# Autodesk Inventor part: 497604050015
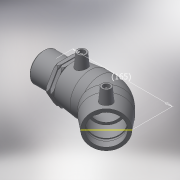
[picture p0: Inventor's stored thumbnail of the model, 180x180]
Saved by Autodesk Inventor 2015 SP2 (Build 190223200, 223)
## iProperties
Created: 2017-06
Part Number: 497604050015
Material: Generic
Description: PLASSON PE MALE TRANSITION 45° ELBOW 50-1.1/2"
Document SubType Name: Modeling
Designer: KIM
Mass: 55.0731 g
Surface Area: 148.067 cm^2
Volume: 55.0731 cm^3
Density: 1 g/cm^3
Appearance: Default
Author: KIM
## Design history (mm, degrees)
derived "497604.ipt"
feature "Solid1::497604.ipt"
tag "TaggingFeature1"
body "Solid1"
other parameters: "d2" = 67, "d4" = 29, "d5" = 60.3, "d8" = 168 deg, "d10" = 18, "d11" = 6, "d29" = 52, "d30" = 15, "d31" = 40.6, "d34" = 5 deg, "d41" = 4, "d42" = 14, "d43" = 0, "d50" = 42.5, "d51" = 18, "d52" = 44.9, "d54" = 135 deg, "d86" = 30.15, "d87" = 135 deg, "d88" = 116, "d90" = 36, "d91" = 0, "d92" = 45, "d93" = 0, "d101" = 3, "d102" = 0, "d107" = 0.1, "d108" = 38, "d109" = 47.803, "d110" = 49, "d111" = 12.25, "d112" = 67, "d113" = 33.4621, "d114" = 44.1, "d116" = 2.01, "d122" = 0, "d123" = 2.39015, "d126" = 1.225, "d127" = 5.5125, "d128" = 67, "d130" = 45, "L_" = 165, "L_2" = 45, "D_" = 38, "A_" = 52, "d_2" = 12, "L_1" = 49, "R_" = 47.803, "D_1" = 67, "d129" = 165
